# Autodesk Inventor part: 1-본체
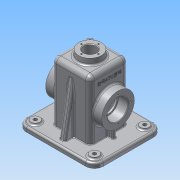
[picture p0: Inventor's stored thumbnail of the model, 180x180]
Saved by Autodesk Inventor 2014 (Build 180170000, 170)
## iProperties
Created: 2015-12
Part Number: 1-본체
Material: 알루미늄 6061
Document SubType Name: Modeling
Designer: Administrator
Density: 2.71 g/cm^3
Appearance: 알루미늄 - 평지
Mass: 803.266 g
Surface Area: 909.178 cm^2
Volume: 296.408 cm^3
Author: Administrator
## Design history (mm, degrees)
sketch "스케치1"
  geometry: L1 (-50, 57.5)-(50, 57.5); L2 (65, 42.5)-(65, -42.5); L3 (50, -57.5)-(-50, -57.5); L4 (-65, -42.5)-(-65, 42.5); L5 (-65, 57.5)-(65, -57.5); L6 (65, 57.5)-(-65, -57.5); A1 r 15 centre (-50, 42.5) between (-50, 57.5) and (-65, 42.5); A2 r 15 centre (-50, -42.5) between (-65, -42.5) and (-50, -57.5); A3 r 15 centre (50, -42.5) between (50, -57.5) and (65, -42.5); A4 r 15 centre (50, 42.5) between (65, 42.5) and (50, 57.5); 1 further point
  constraints: 12 end point, 8 point on circle, 8 point on line, 8 tangent, 4 centre point, 3 equal radius, 2 midpoint, 2 parallel, 1 horizontal, 1 perpendicular
  dimensions: "d0" = 130 distance of L5.start L6.start; "d1" = 115 distance of L6.start L5.end; "d2" = 15 radius of A1
extrude "돌출1" new body sketch "스케치1" distance "d3" = 8; taper "d4" = 0 deg
sketch "스케치2"
  geometry: L1 (50, 57.5)-(-50, 57.5) reference; L2 (-65, 42.5)-(-65, -42.5) reference; L3 (-50, -57.5)-(50, -57.5) reference; L4 (65, -42.5)-(65, 42.5) reference; L5 (-50, 52.5)-(50, 52.5); L6 (60, 42.5)-(60, -42.5); L7 (50, -52.5)-(-50, -52.5); L8 (-60, -42.5)-(-60, 42.5); A1 r 15 centre (-50, 42.5) between (-50, 57.5) and (-65, 42.5) reference; A2 r 15 centre (-50, -42.5) between (-65, -42.5) and (-50, -57.5) reference; A3 r 15 centre (50, -42.5) between (50, -57.5) and (65, -42.5) reference; A4 r 15 centre (50, 42.5) between (65, 42.5) and (50, 57.5) reference; A5 r 10 centre (50, 42.5) between (60, 42.5) and (50, 52.5); A6 r 10 centre (50, -42.5) between (50, -52.5) and (60, -42.5); A7 r 10 centre (-50, -42.5) between (-60, -42.5) and (-50, -52.5); A8 r 10 centre (-50, 42.5) between (-50, 52.5) and (-60, 42.5); 1 further point
  constraints: 8 end point, 8 point on circle, 4 centre point, 7 other
  dimensions: "d5" = 5 distance between parallel lines of L8 L2
extrude "돌출2" join sketch "스케치2" distance "d6" = 2; taper "d7" = 0 deg
sketch "스케치3"
  geometry: L1 (-32.5, 32.5)-(32.5, 32.5); L2 (32.5, 32.5)-(32.5, -32.5); L3 (32.5, -32.5)-(-32.5, -32.5); L4 (-32.5, -32.5)-(-32.5, 32.5); L5 (-32.5, 32.5)-(32.5, -32.5); L6 (32.5, 32.5)-(-32.5, -32.5); 1 further point
  constraints: 12 end point, 2 midpoint, 2 parallel, 2 perpendicular, 1 horizontal
  dimensions: "d8" = 65 distance of L1.start L1.end
extrude "돌출3" join sketch "스케치3" distance "d9" = 100; taper "d10" = 0 deg
sketch "스케치4"
  geometry: C1 r 20 at (0, 0); 1 further point
  constraints: 1 centre point, 1 coincident
  dimensions: "d11" = 40 diameter of C1
extrude "돌출4" join sketch "스케치4" distance "d12" = 10; taper "d13" = -5 deg
hole "구멍1" diameter "d16" = 21; stored, may be unused: countersink angle "d20" = 90 deg, drill point angle "d22" = 118 deg; dims "d14" = 10, "d15" = 10, "d17" = 6, "d18" = 4, "d19" = 2, "d21" = 8
fillet "모깎기1" dims "d23" = 8
node "작업 평면1"
sketch "스케치5"
  geometry: L1 (-10, -18)-(-10, 67) reference; C1 r 27.5 at (45, 24.5); 2 further points
  constraints: 1 centre point, 1 horizontal alignment, 1 midpoint
  dimensions: "d25" = 55 diameter of C1; "d26" = 55 distance from line of C1.centre L1
extrude "돌출5" join sketch "스케치5" stored distance "d27" = 10; taper "d28" = 0 deg
hole "구멍2" diameter "d31" = 35; stored, may be unused: countersink angle "d35" = 90 deg, drill point angle "d37" = 0 deg; dims "d32" = 6, "d33" = 4, "d34" = 2, "d36" = 17, "d125" = 10, "d126" = 10
sketch "스케치6"
  geometry: C1 r 17.5 at (0, 0) reference; C2 r 27.5 at (0, 0) reference; A1 r 21 centre (0, 0) between (21, 0) and (-21, 0); 3 further points
  constraints: 4 point on circle, 2 horizontal alignment, 2 vertical alignment, 1 centre point, 1 coincident
  dimensions: "d38" = 42 diameter of A1
hole "구멍3" sketch "스케치6" at (21, 0), (-21, 0), (0, 21), (0, -21) diameter "d39" = 3.242; stored, may be unused: countersink angle "d43" = 90 deg, drill point angle "d45" = 118 deg; dims "d40" = 8, "d41" = 4, "d42" = 2, "d44" = 10
sketch "스케치7"
  geometry: L1 (-24.5, 27.5)-(24.5, 27.5); L2 (27.5, 24.5)-(27.5, -24.5); L3 (24.5, -27.5)-(-24.5, -27.5); L4 (-27.5, -24.5)-(-27.5, 24.5); L5 (-27.5, 27.5)-(27.5, -27.5); L6 (27.5, 27.5)-(-27.5, -27.5); C1 r 10.5 at (0, 0) reference; A1 r 3 centre (-24.5, 24.5) between (-24.5, 27.5) and (-27.5, 24.5); A2 r 3 centre (24.5, 24.5) between (27.5, 24.5) and (24.5, 27.5); A3 r 3 centre (24.5, -24.5) between (24.5, -27.5) and (27.5, -24.5); A4 r 3 centre (-24.5, -24.5) between (-27.5, -24.5) and (-24.5, -27.5)
  constraints: 12 end point, 8 point on circle, 8 point on line, 8 tangent, 4 centre point, 3 equal radius, 2 midpoint, 2 parallel, 2 perpendicular, 1 horizontal
  dimensions: "d46" = 55 distance of L5.start L6.start; "d47" = 3 radius of A1
extrude "돌출6" cut sketch "스케치7" distance "d48" = 105; taper "d49" = 0 deg
node "작업 평면2"
sketch "스케치8"
  geometry: L1 (100, -8)-(0, -8) reference; L2 (100, -18)-(100, -33) reference; L3 (100, 67)-(100, -18) reference; L4 (100, 82)-(100, 67) reference; L5 (0, 57)-(100, 57) reference; L6 (108, 67)-(108, 82) reference; L7 (100, 72)-(14.931, 57); L8 (108, 82)-(100, 82) reference; 1 further point
  constraints: 2 end point, 2 point on line
  dimensions: "d51" = 10 vertical distance of L6.end L7.start; "d52" = 10 deg angle of L7 L8
extrude "돌출7" join sketch "스케치8" stored distance "d53" = 10; taper "d54" = 0 deg
fillet "모깎기2" dims "d55" = 3
fillet "모깎기3" dims "d56" = 3
node "작업 평면4"
sketch "스케치9"
  geometry: L1 (0, -8)-(-100, -8) reference; L2 (-100, -33)-(-100, -18) reference; L3 (-100, -18)-(-100, 67) reference; L4 (-108, -33)-(-100, -33) reference; L5 (-110, -18)-(-110, -28) reference; L6 (-100, -23)-(-14.931, -8); 1 further point
  constraints: 2 end point, 2 point on line
  dimensions: "d57" = 10 vertical distance of L4.start L6.start; "d58" = 10 deg angle of L4 L6
extrude "돌출8" join sketch "스케치9" stored distance "d59" = 10; taper "d60" = 0 deg
fillet "모깎기4" dims "d61" = 3
fillet "모깎기5" dims "d62" = 3
node "작업 평면5"
sketch "스케치10"
  geometry: L1 (-25.5, 100)-(74.5, 100) reference; L2 (74.5, 100)-(89.5, 100) reference; L3 (57, 100)-(57, 67.49) reference; L4 (57, 82.5)-(72, 82.5) reference; L5 (-8, 67.49)-(-8, 100) reference; L6 (-40.5, 100)-(-25.5, 100) reference; L7 (-40.5, 108)-(-40.5, 100) reference; L8 (89.5, 108)-(89.5, 100) reference; L9 (-23, 82.5)-(-8, 82.5) reference; L10 (67, 100)-(67, 82.5); L11 (52, 110)-(52, 5) reference; L12 (-3, 110)-(-3, 5) reference; L13 (-18, 100)-(-18, 82.5); L14 (-18, 82.5)-(-18, 79.617); L15 (-18, 79.617)-(-8, 79.617); L16 (67, 82.5)-(67, 79.617); L17 (67, 79.617)-(57, 79.617); 1 further point
  constraints: 12 end point, 6 point on line, 4 perpendicular, 1 collinear, 1 parallel
  dimensions: "d64" = 15 horizontal distance of L10.start L11.start; "d65" = 15 horizontal distance of L12.start L13.start
extrude "돌출9" join sketch "스케치10" stored distance "d66" = 6; taper "d67" = 0 deg
sketch "스케치11"
  geometry: C1 r 7.5 at (-50, 42.5); C2 r 7.5 at (50, 42.5); C3 r 7.5 at (50, -42.5); C4 r 7.5 at (-50, -42.5); A1 r 15 centre (-50, 42.5) between (-50, 57.5) and (-65, 42.5) reference; A2 r 15 centre (-50, -42.5) between (-65, -42.5) and (-50, -57.5) reference; A3 r 15 centre (50, -42.5) between (50, -57.5) and (65, -42.5) reference; A4 r 15 centre (50, 42.5) between (65, 42.5) and (50, 57.5) reference; 1 further point
  constraints: 4 centre point, 4 coincident
  dimensions: "d68" = 15 diameter of C1; "d69" = 15 diameter of C4; "d70" = 15 diameter of C2; "d71" = 15 diameter of C3
extrude "돌출10" join sketch "스케치11" distance "d72" = 3; taper "d73" = 0 deg
sketch "스케치12"
  geometry: C1 r 10.5 at (0, 0) reference; C2 r 19.125 at (0, 0) reference; A1 r 14.5 centre (0, 0) between (0, 14.5) and (0, -14.5); 2 further points
  constraints: 4 point on circle, 2 horizontal alignment, 2 vertical alignment, 1 centre point, 1 coincident
  dimensions: "d74" = 29 diameter of A1
hole "구멍4" sketch "스케치12" at (0, 14.5), (0, -14.5), (14.5, 0), (-14.5, 0) diameter "d75" = 2.459; stored, may be unused: countersink angle "d79" = 90 deg, drill point angle "d81" = 118 deg; dims "d76" = 7, "d77" = 4, "d78" = 2, "d80" = 9
hole "구멍5" diameter "d84" = 6; stored, may be unused: countersink angle "d88" = 90 deg, drill point angle "d90" = 0 deg; dims "d82" = 10, "d83" = 10, "d85" = 7, "d86" = 4, "d87" = 2, "d89" = 9
hole "구멍6" diameter "d93" = 6; stored, may be unused: countersink angle "d97" = 90 deg, drill point angle "d99" = 0 deg; dims "d91" = 10, "d92" = 10, "d94" = 7, "d95" = 4, "d96" = 2, "d98" = 9
hole "구멍7" diameter "d102" = 6; stored, may be unused: countersink angle "d106" = 90 deg, drill point angle "d108" = 0 deg; dims "d100" = 10, "d101" = 10, "d103" = 7, "d104" = 4, "d105" = 2, "d107" = 9
hole "구멍8" diameter "d111" = 6; stored, may be unused: countersink angle "d115" = 90 deg, drill point angle "d117" = 0 deg; dims "d109" = 10, "d110" = 10, "d112" = 7, "d113" = 4, "d114" = 2, "d116" = 9
sketch "스케치13"
  geometry: L1 (0, -8)-(100, -8) reference; L2 (-10, 5.375)-(-10, 43.625) reference; 2 further points
  constraints: 1 other
  dimensions: "d118" = 32.5 distance from line of point (16, 24.5) L1; "d119" = 26 horizontal distance of point (16, 24.5) L2.end
feature "엠보싱1" sketch "스케치13" dims "d120" = 0.5, "d121" = 0
fillet "모깎기6" dims "d122" = 8
hole "구멍9" diameter "d127" = 30; stored, may be unused: countersink angle "d131" = 90 deg, drill point angle "d133" = 0 deg; dims "d123" = 10, "d124" = 10, "d128" = 7, "d129" = 4, "d130" = 2, "d132" = 9
fillet "모깎기7" dims "d134" = 3
fillet "모깎기8" dims "d135" = 3
fillet "모깎기9" dims "d136" = 1
chamfer "모따기1" distance "d137" = 1; stored, may be unused: second distance "d138" = 2, angle "d139" = 45 deg
fillet "모깎기10" dims "d140" = 3
fillet "모깎기11" dims "d141" = 0.3
node "솔리드1"
mirror "대칭1"
other parameters: "d24" = 15
